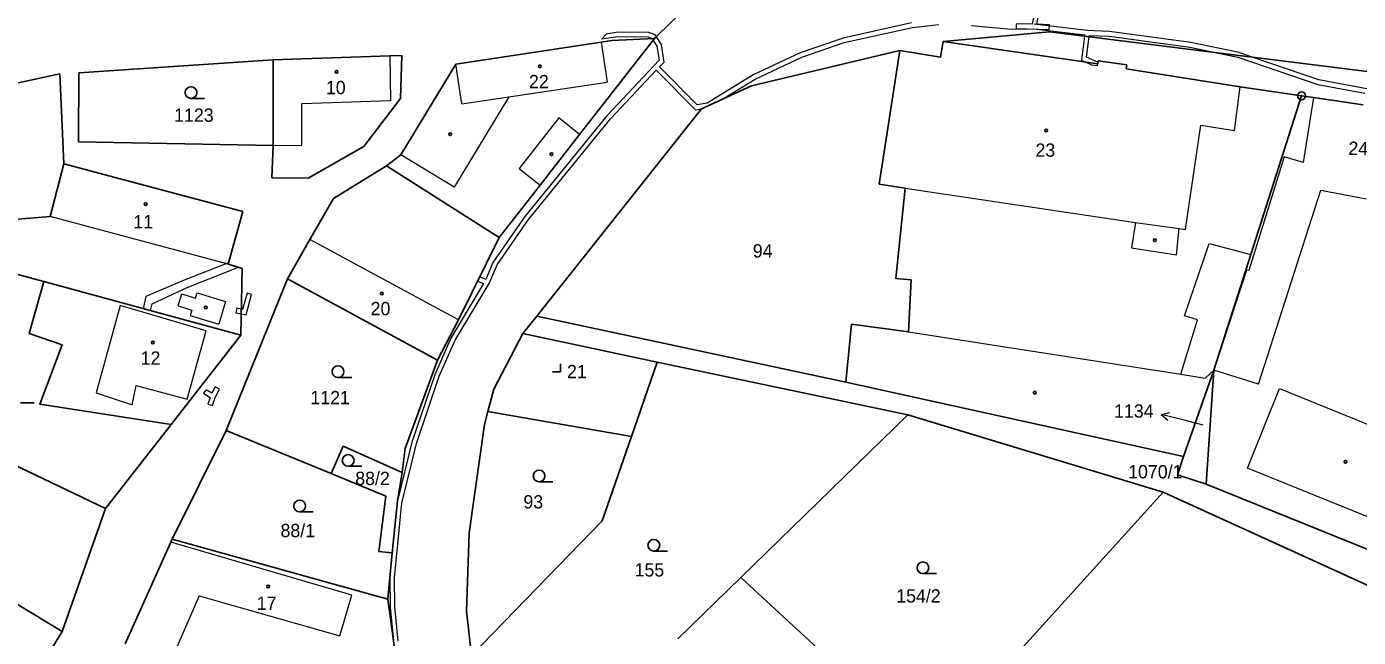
# Model space of a CAD drawing. Extents: x -694609 to -690140, y -1033292 to -1029794.
# Drawn here: x -693128 to -692957.6, y -1031323.3 to -1031245.2 of the extents above; entities that cross this region are included whole.
import ezdxf
from ezdxf.enums import TextEntityAlignment as Align

# ---------------------------------------------------------------- set-up
doc = ezdxf.new("R2010")
doc.units = 0
doc.header["$LTSCALE"] = 0.68
for name, color, linetype, lineweight in [('1', 7, 'Continuous', 25), ('13', 7, 'Continuous', 13), ('3', 7, 'Continuous', 25), ('4', 7, 'Continuous', 13), ('5', 7, 'Continuous', 25), ('7', 7, 'Continuous', 13), ('8', 7, 'Continuous', 25)]:
    doc.layers.add(name, color=color, linetype=linetype, lineweight=lineweight)
doc.layers.add('2', color=7, linetype='Continuous')

msp = doc.modelspace()

# ---------------------------------------------------------------- linework, layer by layer
at = {"layer": '1'}
for p, q in [((-693047.66, -1031246.74), (-693043.14, -1031242.3)), ((-693073.08, -1031250.01), (-693054.5, -1031247.18)), ((-693057.25, -1031259), (-693047.66, -1031246.74)), ((-693054.5, -1031247.18), (-693053.13, -1031246.99)), ((-693053.13, -1031246.99), (-693047.66, -1031246.74)), ((-693010.74, -1031247.1), (-693011.08, -1031249.14)), ((-692997.14, -1031245.89), (-693010.74, -1031247.1)), ((-692990.97, -1031249.99), (-693010.74, -1031247.1)), ((-692946.43, -1031252.19), (-692997.14, -1031245.89)), ((-693096.44, -1031249.44), (-693081.53, -1031248.93)), ((-693080, -1031248.91), (-693081.53, -1031248.93)), ((-693080.16, -1031254.41), (-693080, -1031248.91)), ((-693016.29, -1031248.25), (-693035.27, -1031252.8)), ((-693016.29, -1031248.25), (-693018.94, -1031265.38)), ((-693011.08, -1031249.14), (-693016.29, -1031248.25)), ((-693121.34, -1031251.12), (-693096.44, -1031249.44)), ((-693096.45, -1031260.41), (-693096.44, -1031249.44)), ((-693080.14, -1031261.62), (-693073.08, -1031250.01)), ((-692990.93, -1031249.6), (-692990.97, -1031249.99)), ((-692987.26, -1031250.12), (-692990.93, -1031249.6)), ((-692987.34, -1031250.62), (-692987.26, -1031250.12)), ((-692972.76, -1031252.91), (-692987.34, -1031250.62)), ((-693133.94, -1031253.47), (-693123.76, -1031251.26)), ((-693123.23, -1031262.78), (-693123.76, -1031251.26)), ((-693121.35, -1031259.97), (-693121.34, -1031251.12)), ((-693035.27, -1031252.8), (-693041.65, -1031255.71)), ((-692972.76, -1031252.91), (-692964.9, -1031254.06)), ((-692971.4, -1031274.38), (-692964.9, -1031254.06)), ((-692963.38, -1031254.29), (-692964.9, -1031254.06)), ((-693084.85, -1031260.53), (-693080.16, -1031254.41)), ((-693041.65, -1031255.71), (-693062.75, -1031282.24)), ((-692957.02, -1031255.21), (-692963.38, -1031254.29)), ((-693062.32, -1031265.49), (-693057.25, -1031259)), ((-693096.45, -1031260.41), (-693121.35, -1031259.97)), ((-693096.45, -1031260.41), (-693096.63, -1031264.55)), ((-693091.97, -1031264.6), (-693084.85, -1031260.53)), ((-693081.94, -1031263), (-693080.14, -1031261.62)), ((-693124.97, -1031269.5), (-693123.23, -1031262.78)), ((-693100.36, -1031268.87), (-693123.23, -1031262.78)), ((-693081.94, -1031263), (-693088.76, -1031267.2)), ((-693067.55, -1031272.17), (-693081.94, -1031263)), ((-693096.63, -1031264.55), (-693091.97, -1031264.6)), ((-693067.55, -1031272.17), (-693062.32, -1031265.49)), ((-693018.94, -1031265.38), (-693015.63, -1031265.87)), ((-693015.63, -1031265.87), (-693016.8, -1031277.41)), ((-693088.76, -1031267.2), (-693091.75, -1031272.44)), ((-693102.2, -1031275.58), (-693100.36, -1031268.87)), ((-693129.11, -1031269.84), (-693124.97, -1031269.5)), ((-693091.75, -1031272.44), (-693094.64, -1031277.49)), ((-693067.55, -1031272.17), (-693072.73, -1031282.73)), ((-692976.13, -1031289.15), (-692971.4, -1031274.38)), ((-693100.42, -1031276.14), (-693102.2, -1031275.58)), ((-693100.61, -1031284.68), (-693100.42, -1031276.14)), ((-693130.41, -1031276.57), (-693125.78, -1031277.83)), ((-693125.78, -1031277.83), (-693100.61, -1031284.68)), ((-693094.64, -1031277.49), (-693102.46, -1031296.87)), ((-693075.45, -1031287.87), (-693094.64, -1031277.49)), ((-693016.8, -1031277.41), (-693014.84, -1031277.58)), ((-693014.84, -1031277.58), (-693015.18, -1031284.25)), ((-693075.45, -1031287.87), (-693072.73, -1031282.73)), ((-693062.75, -1031282.24), (-693064.53, -1031284.48)), ((-693062.75, -1031282.24), (-693023.2, -1031290.68)), ((-693100.61, -1031284.68), (-693109.52, -1031296.11)), ((-693064.53, -1031284.48), (-693068.25, -1031291.6)), ((-693064.53, -1031284.48), (-693047.32, -1031288.11)), ((-693023.2, -1031290.68), (-693022.46, -1031283.27)), ((-693015.18, -1031284.25), (-693022.46, -1031283.27)), ((-693079.59, -1031299.19), (-693075.45, -1031287.87)), ((-693050.64, -1031297.65), (-693047.32, -1031288.11)), ((-693047.32, -1031288.11), (-693015.28, -1031294.87)), ((-692976.13, -1031289.15), (-692980.02, -1031300.21)), ((-692977.11, -1031303.75), (-692976.13, -1031289.15)), ((-693023.2, -1031290.68), (-692980.02, -1031300.21)), ((-693068.25, -1031291.6), (-693068.99, -1031294.43)), ((-693068.99, -1031294.43), (-693069.44, -1031296.12)), ((-693068.99, -1031294.43), (-693050.64, -1031297.65)), ((-693036.63, -1031315.66), (-693015.28, -1031294.87)), ((-692982.62, -1031304.77), (-693015.28, -1031294.87)), ((-693109.52, -1031296.11), (-693117.89, -1031306.85)), ((-693069.44, -1031296.12), (-693071.38, -1031309.94)), ((-693137.56, -1031297.47), (-693117.89, -1031306.85)), ((-693109.37, -1031310.77), (-693102.46, -1031296.87)), ((-693102.46, -1031296.87), (-693089.06, -1031302.36)), ((-693054.38, -1031308.42), (-693050.64, -1031297.65)), ((-693089.06, -1031302.36), (-693087.52, -1031298.88)), ((-693079.94, -1031302.23), (-693087.52, -1031298.88)), ((-693079.94, -1031302.23), (-693079.59, -1031299.19)), ((-693089.06, -1031302.36), (-693082.06, -1031305.29)), ((-693080.56, -1031305.85), (-693079.94, -1031302.23)), ((-693011.32, -1031336.45), (-692982.62, -1031304.77)), ((-692944.79, -1031321.99), (-692982.62, -1031304.77)), ((-692951.8, -1031313.97), (-692977.11, -1031303.75)), ((-693117.89, -1031306.85), (-693123.43, -1031322.59)), ((-693082.93, -1031312.33), (-693082.06, -1031305.29)), ((-693080.56, -1031305.85), (-693081.22, -1031312.51)), ((-693071.07, -1031325.64), (-693054.38, -1031308.42)), ((-693071.38, -1031309.94), (-693071.72, -1031320)), ((-693143.16, -1031310.61), (-693123.43, -1031322.59)), ((-693109.53, -1031311.17), (-693115.38, -1031324.14)), ((-693109.53, -1031311.17), (-693109.37, -1031310.77)), ((-693081.81, -1031318.46), (-693109.37, -1031310.77)), ((-693081.22, -1031312.51), (-693082.93, -1031312.33)), ((-693081.22, -1031312.51), (-693081.81, -1031318.46)), ((-693044.7, -1031323.52), (-693036.63, -1031315.66)), ((-693032.19, -1031319.75), (-693036.63, -1031315.66)), ((-693081.81, -1031318.46), (-693080.06, -1031331.16)), ((-693071.72, -1031320), (-693071.07, -1031325.64)), ((-693032.19, -1031319.75), (-693021.16, -1031329.91)), ((-693123.43, -1031322.59), (-693138.69, -1031347.09))]:
    msp.add_line(p, q, dxfattribs=at)
for points in [[(-693125.78, -1031277.83), (-693127.66, -1031284.45), (-693123.47, -1031285.9), (-693126.32, -1031293.5), (-693109.52, -1031296.11)], [(-692980.02, -1031300.21), (-692980.77, -1031302.54), (-692977.11, -1031303.75)]]:
    msp.add_lwpolyline(points, dxfattribs=at)
at = {"layer": '13'}
for points in [[(-692997.18, -1031245.6), (-692997.14, -1031245), (-692998.77, -1031244.9), (-692996.69, -1031234.66), (-692997.28, -1031234.54), (-692999.37, -1031244.88), (-693001.43, -1031244.86), (-693001.43, -1031245.46)], [(-693047.58, -1031246.27), (-693048.39, -1031245.95), (-693052.34, -1031245.94), (-693053.84, -1031246.17), (-693054.41, -1031246.78), (-693052.34, -1031246.48), (-693048.49, -1031246.51), (-693047.98, -1031246.75), (-693047.66, -1031246.74), (-693047.43, -1031246.51)], [(-692991.77, -1031250.08), (-692991, -1031250.19), (-692990.97, -1031249.99), (-692990.95, -1031249.76), (-692992.4, -1031249.14), (-692992.06, -1031246.52), (-692992.65, -1031246.45), (-692993.06, -1031249.52), (-692992.49, -1031249.77)], [(-693112.14, -1031281.54), (-693111.95, -1031280.68), (-693107.44, -1031278.58), (-693100.89, -1031275.99), (-693102.2, -1031275.58), (-693102.16, -1031275.42), (-693107.85, -1031277.66), (-693112.75, -1031279.75), (-693113.09, -1031281.29)], [(-693113.09, -1031281.29), (-693112.14, -1031281.54), (-693111.95, -1031280.68), (-693107.44, -1031278.58), (-693100.89, -1031275.99), (-693102.2, -1031275.58), (-693102.16, -1031275.42), (-693107.85, -1031277.66), (-693112.75, -1031279.75)], [(-693099.93, -1031282.08), (-693099.21, -1031279.46), (-693099.79, -1031279.3), (-693100.37, -1031281.38), (-693100.54, -1031281.35), (-693100.55, -1031281.96)], [(-693101.12, -1031281.24), (-693101.23, -1031281.83), (-693100.55, -1031281.96), (-693100.54, -1031281.35)], [(-693103.89, -1031292.64), (-693103.34, -1031291.57), (-693103.87, -1031291.3), (-693104.29, -1031292.11), (-693105.01, -1031291.65), (-693105.39, -1031292.11), (-693104.53, -1031292.66), (-693104.8, -1031293.5), (-693104.23, -1031293.69)]]:
    msp.add_lwpolyline(points, close=True, dxfattribs=at)
for points in [[(-693014.79, -1031244.73), (-693023.56, -1031246.67), (-693029.05, -1031248.58), (-693035.06, -1031251.4), (-693040.94, -1031255.01), (-693042.21, -1031255.2), (-693047.03, -1031250.36), (-693046.44, -1031249.76), (-693046.8, -1031247.48), (-693047.43, -1031246.51), (-693047.66, -1031246.74), (-693047.85, -1031246.98), (-693047.38, -1031247.7), (-693047.08, -1031249.51), (-693053.77, -1031256.61), (-693064.28, -1031269.52), (-693068.34, -1031275.39), (-693069.26, -1031277.54), (-693070.03, -1031277.23), (-693070.3, -1031277.78), (-693069.54, -1031278.09), (-693073.73, -1031285.05), (-693075.79, -1031289.73), (-693078.7, -1031298.38), (-693080.56, -1031305.85), (-693081.22, -1031312.51), (-693081.53, -1031315.68), (-693081.51, -1031319.46), (-693081.08, -1031323.75)], [(-693078.12, -1031298.54), (-693075.23, -1031289.94), (-693073.19, -1031285.33), (-693068.83, -1031278.07), (-693067.82, -1031275.69), (-693063.8, -1031269.88), (-693053.32, -1031257), (-693047.46, -1031250.77), (-693042.43, -1031255.84), (-693041.65, -1031255.71), (-693038.83, -1031254.42), (-693034.78, -1031251.94), (-693028.81, -1031249.13), (-693023.4, -1031247.25), (-693014.69, -1031245.32), (-693011.3, -1031244.96)], [(-693007.17, -1031245.08), (-693002.02, -1031245.55), (-692999.15, -1031245.48), (-692992.63, -1031246.27), (-692992.65, -1031246.45), (-692992.06, -1031246.52), (-692992.03, -1031246.33), (-692989.49, -1031246.43), (-692979.19, -1031247.83), (-692975.76, -1031248.55), (-692971.21, -1031249.11), (-692972.9, -1031248.53), (-692979.08, -1031247.24), (-692989.45, -1031245.83), (-692992.34, -1031245.72), (-692999.12, -1031244.88)], [(-692956.55, -1031253.16), (-692962.69, -1031252.04), (-692971.21, -1031249.11), (-692975.76, -1031248.55), (-692973.06, -1031249.11), (-692962.84, -1031252.62), (-692956.81, -1031253.72)], [(-693080.45, -1031323.83), (-693080.91, -1031319.43), (-693080.95, -1031315.71), (-693080, -1031306.18), (-693078.12, -1031298.54)]]:
    msp.add_lwpolyline(points, dxfattribs=at)
at = {"layer": '3'}
for p, q in [((-693106.973, -1031254.4), (-693105.223, -1031254.4)), ((-693088.163, -1031290.1), (-693086.413, -1031290.1)), ((-693128.773, -1031293.33), (-693127.023, -1031293.33)), ((-693086.863, -1031301.45), (-693085.113, -1031301.45)), ((-693062.443, -1031303.43), (-693060.693, -1031303.43)), ((-693093.073, -1031307.28), (-693091.323, -1031307.28)), ((-693047.763, -1031312.3), (-693046.013, -1031312.3)), ((-693013.343, -1031315.18), (-693011.593, -1031315.18))]:
    msp.add_line(p, q, dxfattribs=at)
msp.add_lwpolyline([(-693060.711, -1031289.35), (-693059.71, -1031289.35), (-693059.71, -1031288.35)], dxfattribs=at)
for centre in [(-693106.9729, -1031253.6498), (-693088.1629, -1031289.3498), (-693086.8629, -1031300.6998), (-693062.4429, -1031302.6798), (-693093.0729, -1031306.5298), (-693047.7629, -1031311.5498), (-693013.3429, -1031314.4298)]:
    msp.add_circle(centre, 0.75, dxfattribs=at)
at = {"layer": '4'}
for p, q in [((-693054.5, -1031247.18), (-693053.73, -1031252.32)), ((-693081.53, -1031248.93), (-693081.47, -1031254.69)), ((-693072.31, -1031255.1), (-693073.08, -1031250.01)), ((-693066.29, -1031254.2), (-693053.73, -1031252.32)), ((-693081.47, -1031254.69), (-693092.78, -1031255.08)), ((-693066.29, -1031254.2), (-693073.32, -1031265.76)), ((-693072.31, -1031255.1), (-693066.29, -1031254.2)), ((-692963.38, -1031254.29), (-692964.69, -1031262.59)), ((-693057.25, -1031259), (-693059.92, -1031256.9)), ((-693073.32, -1031265.76), (-693080.14, -1031261.62)), ((-693015.63, -1031265.87), (-692986.14, -1031270.25)), ((-692970.41, -1031290.93), (-692962.43, -1031266.14)), ((-692962.43, -1031266.14), (-692956.65, -1031267.24)), ((-693102.2, -1031275.58), (-693124.97, -1031269.5)), ((-692986.14, -1031270.25), (-692986.65, -1031273.51)), ((-692986.14, -1031270.25), (-692980.57, -1031271.03)), ((-692980.88, -1031274.4), (-692980.57, -1031271.03)), ((-692980.57, -1031271.03), (-692979.73, -1031271.16)), ((-693072.73, -1031282.73), (-693091.75, -1031272.44)), ((-692986.65, -1031273.51), (-692980.88, -1031274.4)), ((-692979.87, -1031282.22), (-692976.74, -1031272.95)), ((-692976.74, -1031272.95), (-692971.4, -1031274.38)), ((-692971.95, -1031276.38), (-692976.13, -1031289.15)), ((-692971.63, -1031276.39), (-692971.95, -1031276.38)), ((-693108.63, -1031280.94), (-693108.16, -1031279.41)), ((-693108.16, -1031279.41), (-693106.39, -1031279.95)), ((-693106.39, -1031279.95), (-693106.18, -1031279.28)), ((-693106.18, -1031279.28), (-693102.55, -1031280.39)), ((-693108.63, -1031280.94), (-693106.86, -1031281.48)), ((-693102.55, -1031280.39), (-693103.43, -1031283.26)), ((-692978.2, -1031282.72), (-692979.87, -1031282.22)), ((-692980.33, -1031289.68), (-692977.25, -1031290.16)), ((-692977.25, -1031290.16), (-692976.13, -1031289.15)), ((-692970.41, -1031290.93), (-692976.13, -1031289.15)), ((-693086.39, -1031317.93), (-693109.53, -1031311.17)), ((-693105.91, -1031318.03), (-693109.66, -1031326.65)), ((-693105.91, -1031318.03), (-693087.91, -1031323.14)), ((-693087.91, -1031323.14), (-693086.39, -1031317.93))]:
    msp.add_line(p, q, dxfattribs=at)
for points in [[(-692979.73, -1031271.16), (-692977.79, -1031257.81), (-692973.48, -1031258.48), (-692972.76, -1031252.91)], [(-693096.45, -1031260.41), (-693092.79, -1031260.38), (-693092.78, -1031255.08)], [(-693059.92, -1031256.9), (-693064.99, -1031263.38), (-693062.32, -1031265.49)], [(-692964.69, -1031262.59), (-692967.11, -1031261.85), (-692971.63, -1031276.39)], [(-693106.86, -1031281.48), (-693107.06, -1031282.15), (-693103.43, -1031283.26)], [(-693015.18, -1031284.25), (-692980.33, -1031289.68), (-692978.2, -1031282.72)]]:
    msp.add_lwpolyline(points, dxfattribs=at)
for points in [[(-693116.03, -1031280.87), (-693119.11, -1031292.05), (-693114.51, -1031293.57), (-693113.98, -1031291.13), (-693107.44, -1031292.86), (-693105.03, -1031284.13)], [(-692971.82, -1031301.71), (-692967.72, -1031291.51), (-692946.84, -1031299.97), (-692950.98, -1031310.11)]]:
    msp.add_lwpolyline(points, close=True, dxfattribs=at)
at = {"layer": '5'}
for centre in [(-693062.3368, -1031250.2892), (-693088.3468, -1031250.9992), (-693073.8168, -1031258.9692), (-692997.5768, -1031258.5092), (-693060.8368, -1031261.5292), (-693112.7668, -1031267.9192), (-692983.6768, -1031272.5292), (-693082.5568, -1031279.3492), (-693105.0868, -1031281.1392), (-693111.8468, -1031285.6292), (-692999.0368, -1031292.0292), (-692959.2968, -1031300.8692), (-693097.0868, -1031316.8192)]:
    msp.add_circle(centre, 0.175, dxfattribs=at)
at = {"layer": '7'}
msp.add_line((-692982.842, -1031294.824), (-692981.991, -1031295.552), dxfattribs=at)
msp.add_lwpolyline([(-692977.48, -1031296.18), (-692979.93, -1031295.55), (-692982.842, -1031294.824), (-692981.749, -1031294.58)], dxfattribs=at)
at = {"layer": '8'}
for radius in [0.5, 0.0303]:
    msp.add_circle((-692964.9, -1031254.0599), radius, dxfattribs=at)

# ---------------------------------------------------------------- texts
at = {"layer": '2'}
for s, p in [('10', (-693088.449, -1031253.855)), ('22', (-693062.469, -1031253.095)), ('1123', (-693106.6, -1031257.385)), ('23', (-692997.679, -1031261.855)), ('11', (-693113.089, -1031271.025)), ('94', (-693033.839, -1031274.745)), ('20', (-693082.729, -1031282.125)), ('12', (-693112.149, -1031288.455)), ('21', (-693057.609, -1031290.185)), ('1121', (-693089.17, -1031293.515)), ('1070/1', (-692983.61, -1031302.995)), ('88/2', (-693083.749, -1031303.845)), ('93', (-693063.179, -1031306.845)), ('88/1', (-693093.309, -1031310.515)), ('155', (-693048.329, -1031315.545)), ('154/2', (-693013.91, -1031318.875)), ('17', (-693097.299, -1031319.815))]:
    msp.add_text(s, height=1.7, dxfattribs=at).set_placement(p, align=Align.CENTER)
msp.add_text('24/1', height=1.7, rotation=358, dxfattribs=at).set_placement((-692958.944, -1031261.604))
msp.add_text('1134', height=1.7, dxfattribs=at).set_placement((-692983.83, -1031295.225), align=Align.RIGHT)

doc.saveas('drawing.dxf')
